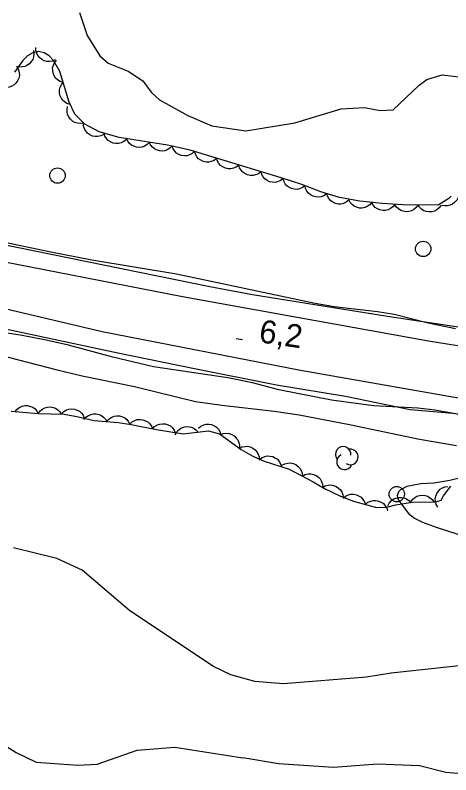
# Model space of a CAD drawing. Extents: x 336540 to 340074, y 5572036 to 5573747.
# Drawn here: x 336923.4 to 336980, y 5572520.4 to 5572619 of the extents above; entities that cross this region are included whole.
import ezdxf

# ---------------------------------------------------------------- set-up
doc = ezdxf.new("R2010")
doc.units = 0
for name, color, linetype in [('Niveau 1', 7, 'Continuous'), ('Niveau 2', 7, 'Continuous'), ('Niveau 21', 7, 'Continuous'), ('Niveau 22', 7, 'Continuous'), ('Niveau 3', 7, 'Continuous'), ('Niveau 36', 7, 'Continuous'), ('Niveau 44', 7, 'Continuous')]:
    doc.layers.add(name, color=color, linetype=linetype)

msp = doc.modelspace()

# ---------------------------------------------------------------- linework, layer by layer
at = {"layer": 'Niveau 1'}
for points in [[(336931.73, 5572619.39), (336932.73, 5572616.38), (336934.39, 5572613.75), (336935.46, 5572612.78), (336938.06, 5572611.74), (336939.97, 5572610.49), (336941.06, 5572609.02), (336942.14, 5572608.04), (336945.79, 5572606.02), (336948.91, 5572604.65), (336953.33, 5572604.03), (336959.72, 5572605.04), (336965.72, 5572606.88), (336968.76, 5572607.04), (336970.8, 5572606.64)], [(336970.8, 5572606.64), (336972.48, 5572606.72), (336975.86, 5572609.93), (336976.85, 5572610.67), (336978.84, 5572611.27), (336982.76, 5572610.81)], [(336981.61, 5572559.04), (336979.84, 5572558.63), (336977.75, 5572558.28), (336976.08, 5572558.18), (336974.23, 5572557.85), (336973.42, 5572557.4), (336973.18, 5572557.17), (336973.01, 5572556.65), (336973.12, 5572556.12), (336974.44, 5572554.35), (336975.25, 5572553.73), (336976.27, 5572553.23), (336978.04, 5572552.57), (336983.66, 5572550.75)], [(336981.45, 5572534.59), (336972.2, 5572533.6), (336969.01, 5572533.11), (336958.23, 5572532.21), (336954.5, 5572532.53), (336951.4, 5572533.39), (336949.15, 5572534.46), (336938.28, 5572541.7), (336932.09, 5572546.97), (336928.79, 5572548.5), (336923.15, 5572549.9)], [(336874.51, 5572538.08), (336878.52, 5572539.31), (336880.05, 5572539.4), (336881.19, 5572539.95), (336882.71, 5572540.03), (336886.84, 5572538.71), (336888.86, 5572538.48), (336893.41, 5572539.05), (336896.45, 5572539.21), (336906.09, 5572536.15), (336907.31, 5572535.37), (336909.87, 5572534.8), (336911.8, 5572533.72), (336913.62, 5572531.27), (336914.36, 5572529.77), (336918.06, 5572526.75), (336923.5, 5572523.3), (336926.1, 5572522.07), (336931.54, 5572521.68), (336934.05, 5572521.82), (336939.22, 5572523.61), (336944.12, 5572524.02), (336952.96, 5572522.62)], [(336982.88, 5572520.42), (336979.29, 5572520.74), (336975.87, 5572521.59), (336970.44, 5572521.81), (336964.71, 5572521.35), (336957.57, 5572521.83), (336952.96, 5572522.62)]]:
    msp.add_lwpolyline(points, dxfattribs=at)
at = {"layer": 'Niveau 2'}
for points in [[(336860.36, 5572601.83), (336879.35, 5572598.2), (336888.35, 5572596.03), (336898.9, 5572593.98), (336904.91, 5572592.45), (336907.38, 5572591.96), (336917.84, 5572590.34), (336921.41, 5572589.69), (336927.81, 5572588.33), (336933.34, 5572587.27), (336944.32, 5572585.43), (336962.33, 5572581.62), (336964.82, 5572581.19), (336970.45, 5572580.58), (336972.58, 5572580.22), (336977.03, 5572579.08), (336980.56, 5572578.37)], [(336981.03, 5572567.18), (336977.9, 5572567.75), (336975.68, 5572568.01), (336969.91, 5572568.32), (336964.45, 5572569.03), (336957.63, 5572570.41), (336954.21, 5572571.29), (336951.01, 5572571.97), (336941.34, 5572573.38), (336936.05, 5572574.63), (336930.31, 5572576.17), (336927.4, 5572576.85), (336924.3, 5572577.44), (336909.1, 5572579.76), (336905.85, 5572580.4), (336893.36, 5572583.16), (336889.93, 5572583.82), (336877.38, 5572586.6), (336870.87, 5572587.91), (336857.82, 5572590.05)]]:
    msp.add_lwpolyline(points, dxfattribs=at)
at = {"layer": 'Niveau 21'}
for points in [[(337100.64, 5572555), (337088.68, 5572555.77), (337076.26, 5572556.91), (337061.77, 5572558.48), (337053.08, 5572559.51), (337036.48, 5572561.54), (337019.9, 5572563.72), (337003.65, 5572566.07), (336997.26, 5572566.87), (336981.42, 5572569.24), (336960.45, 5572572.91), (336934.7, 5572577.9), (336922.06, 5572580.9), (336896.11, 5572586.22), (336883.84, 5572588.4), (336824.78, 5572600.58), (336808.76, 5572603.44), (336772.56, 5572611.03), (336750.71, 5572615.17), (336667.09, 5572632.55), (336658.39, 5572633.88), (336648.84, 5572635.99), (336623.94, 5572640.52), (336607.07, 5572643.16)], [(337095.79, 5572561.86), (337085.79, 5572562.64), (337061.8, 5572564.95), (337045.61, 5572566.7), (337035.77, 5572567.94), (337006.72, 5572571.94), (336977.04, 5572576.7), (336945.1, 5572582.45), (336884.31, 5572594.33), (336807.63, 5572610.39)], [(336854.11, 5572603.04), (336864.11, 5572601.24), (336873.61, 5572598.85), (336882.78, 5572596.77), (336912.98, 5572591.14), (336921.22, 5572589.38), (336948.66, 5572583.79), (336954.19, 5572582.77), (336971.74, 5572579.97), (336983.82, 5572578.15), (337013.25, 5572573.26), (337050.14, 5572568.44), (337060.73, 5572567.18), (337067.1, 5572566.52), (337092.27, 5572564.2)], [(336862, 5572590.65), (336871.76, 5572588.24), (336879.75, 5572586.54), (336884.48, 5572585.66), (336895.01, 5572583.94), (336909.33, 5572581.03), (336936.73, 5572575.18), (336946.66, 5572573.14), (336957.31, 5572571.04), (336966.26, 5572569.58), (336974.67, 5572567.84), (336980.22, 5572567.35), (336984.21, 5572566.84), (336990.44, 5572565.82), (336999.21, 5572564.62), (337006.58, 5572563.3), (337073.99, 5572555.28), (337110.67, 5572552.6)]]:
    msp.add_lwpolyline(points, dxfattribs=at)
at = {"layer": 'Niveau 22'}
msp.add_lwpolyline([(336858.5, 5572587.06), (336869.42, 5572585.02), (336878.23, 5572582.93), (336880.94, 5572582.36), (336884.08, 5572581.82), (336890.68, 5572580.93), (336900.3, 5572578.97), (336912.93, 5572576.76), (336916.31, 5572576.08), (336918.74, 5572575.58), (336928.85, 5572572.98), (336932.08, 5572572.22), (336938.89, 5572570.82), (336946.81, 5572568.87), (336950.22, 5572568.38), (336957.03, 5572567.64), (336960.26, 5572567.15), (336966.82, 5572565.9), (336975.89, 5572564), (336980.68, 5572563.17)], dxfattribs=at)
at = {"layer": 'Niveau 3'}
msp.add_line((336952.1, 5572577.04), (336952.89, 5572576.92), dxfattribs=at)
at = {"layer": 'Niveau 36'}
for centre in [(336928.889, 5572598.201), (336976.369, 5572588.681), (336972.939, 5572556.851)]:
    msp.add_circle(centre, 1, dxfattribs=at)
at = {"layer": 'Niveau 44'}
for points in [[(336928.62, 5572613.23), (336928.24, 5572613.06), (336927.84, 5572613.01), (336927.51, 5572613.01), (336927.17, 5572613.11), (336926.84, 5572613.28), (336926.56, 5572613.53), (336926.33, 5572613.77), (336926.19, 5572614.09), (336926.09, 5572614.45), (336926.08, 5572614.81)], [(336980, 5572595.52), (336979.71, 5572595.23), (336978.33, 5572594.36), (336973.74, 5572594.41), (336971.02, 5572594.58), (336968.13, 5572594.89), (336965.49, 5572595.37), (336963.06, 5572596.11), (336960.6, 5572597.03), (336957.91, 5572597.9), (336946.12, 5572601.48), (336943.18, 5572602.15), (336936.9, 5572603.14), (336934.31, 5572603.86), (336932.44, 5572604.86), (336931.15, 5572606.19), (336930.42, 5572607.72), (336929.18, 5572611.72), (336928.36, 5572613.16), (336927.8, 5572613.74), (336927.14, 5572614.15), (336926.43, 5572614.29), (336925.69, 5572614.12), (336925.01, 5572613.73), (336924.4, 5572613.16), (336923.28, 5572611.63)], [(336925.75, 5572614.42), (336925.82, 5572614.01), (336925.76, 5572613.61), (336925.67, 5572613.29), (336925.48, 5572612.99), (336925.24, 5572612.72), (336924.92, 5572612.5), (336924.63, 5572612.35), (336924.28, 5572612.3), (336923.91, 5572612.29), (336923.56, 5572612.37)], [(336929.63, 5572610.28), (336929.23, 5572610.4), (336928.89, 5572610.63), (336928.64, 5572610.85), (336928.45, 5572611.14), (336928.31, 5572611.49), (336928.26, 5572611.87), (336928.25, 5572612.19), (336928.35, 5572612.53), (336928.51, 5572612.87), (336928.74, 5572613.15)], [(336923.62, 5572612.29), (336923.82, 5572611.92), (336923.9, 5572611.52), (336923.93, 5572611.19), (336923.85, 5572610.85), (336923.71, 5572610.51), (336923.47, 5572610.2), (336923.25, 5572609.97), (336922.94, 5572609.8), (336922.59, 5572609.67), (336922.24, 5572609.63)], [(336930.51, 5572607.42), (336930.11, 5572607.54), (336929.78, 5572607.76), (336929.53, 5572607.98), (336929.34, 5572608.28), (336929.2, 5572608.62), (336929.15, 5572609), (336929.14, 5572609.33), (336929.24, 5572609.67), (336929.4, 5572610), (336929.63, 5572610.28)], [(336932.28, 5572605.02), (336931.87, 5572604.95), (336931.47, 5572605), (336931.15, 5572605.08), (336930.84, 5572605.26), (336930.56, 5572605.51), (336930.35, 5572605.82), (336930.19, 5572606.11), (336930.13, 5572606.46), (336930.12, 5572606.83), (336930.19, 5572607.18)], [(336934.88, 5572603.55), (336934.51, 5572603.36), (336934.11, 5572603.28), (336933.78, 5572603.26), (336933.44, 5572603.34), (336933.1, 5572603.49), (336932.8, 5572603.72), (336932.56, 5572603.95), (336932.4, 5572604.26), (336932.28, 5572604.61), (336932.24, 5572604.97)], [(336937.83, 5572602.88), (336937.51, 5572602.61), (336937.14, 5572602.45), (336936.82, 5572602.36), (336936.47, 5572602.36), (336936.1, 5572602.43), (336935.76, 5572602.59), (336935.48, 5572602.76), (336935.25, 5572603.03), (336935.05, 5572603.34), (336934.94, 5572603.69)], [(336940.81, 5572602.52), (336940.53, 5572602.22), (336940.18, 5572602.01), (336939.87, 5572601.89), (336939.52, 5572601.85), (336939.15, 5572601.88), (336938.79, 5572602), (336938.49, 5572602.14), (336938.23, 5572602.37), (336938, 5572602.66), (336937.85, 5572602.99)], [(336943.78, 5572602.06), (336943.49, 5572601.75), (336943.14, 5572601.55), (336942.83, 5572601.42), (336942.48, 5572601.38), (336942.12, 5572601.41), (336941.75, 5572601.53), (336941.46, 5572601.67), (336941.2, 5572601.91), (336940.97, 5572602.2), (336940.81, 5572602.52)], [(336946.69, 5572601.35), (336946.39, 5572601.06), (336946.02, 5572600.88), (336945.71, 5572600.78), (336945.36, 5572600.77), (336944.99, 5572600.82), (336944.64, 5572600.96), (336944.35, 5572601.12), (336944.11, 5572601.37), (336943.9, 5572601.68), (336943.77, 5572602.02)], [(336949.55, 5572600.44), (336949.23, 5572600.17), (336948.85, 5572600.02), (336948.53, 5572599.94), (336948.18, 5572599.95), (336947.82, 5572600.03), (336947.48, 5572600.2), (336947.2, 5572600.37), (336946.98, 5572600.64), (336946.79, 5572600.97), (336946.68, 5572601.31)], [(336952.42, 5572599.57), (336952.1, 5572599.3), (336951.72, 5572599.15), (336951.4, 5572599.07), (336951.05, 5572599.08), (336950.69, 5572599.16), (336950.35, 5572599.33), (336950.07, 5572599.5), (336949.85, 5572599.77), (336949.66, 5572600.09), (336949.55, 5572600.44)], [(336955.29, 5572598.69), (336954.97, 5572598.43), (336954.59, 5572598.28), (336954.27, 5572598.2), (336953.92, 5572598.21), (336953.56, 5572598.28), (336953.22, 5572598.46), (336952.94, 5572598.63), (336952.72, 5572598.9), (336952.53, 5572599.22), (336952.42, 5572599.57)], [(336958.17, 5572597.82), (336957.84, 5572597.56), (336957.46, 5572597.41), (336957.14, 5572597.32), (336956.79, 5572597.34), (336956.43, 5572597.41), (336956.09, 5572597.58), (336955.81, 5572597.76), (336955.59, 5572598.03), (336955.4, 5572598.35), (336955.29, 5572598.69)], [(336961.02, 5572596.89), (336960.69, 5572596.64), (336960.31, 5572596.49), (336959.99, 5572596.41), (336959.64, 5572596.43), (336959.28, 5572596.52), (336958.94, 5572596.69), (336958.67, 5572596.87), (336958.45, 5572597.15), (336958.26, 5572597.47), (336958.16, 5572597.82)], [(336963.82, 5572595.83), (336963.48, 5572595.58), (336963.1, 5572595.45), (336962.77, 5572595.39), (336962.42, 5572595.43), (336962.07, 5572595.53), (336961.73, 5572595.72), (336961.47, 5572595.91), (336961.26, 5572596.19), (336961.1, 5572596.53), (336961.01, 5572596.88)], [(336980.94, 5572596.46), (336981.02, 5572596.05), (336980.97, 5572595.64), (336980.9, 5572595.32), (336980.72, 5572595.02), (336980.48, 5572594.74), (336980.17, 5572594.51), (336979.89, 5572594.35), (336979.54, 5572594.28), (336979.17, 5572594.27), (336978.82, 5572594.34)], [(336966.71, 5572595), (336966.38, 5572594.74), (336966.01, 5572594.58), (336965.69, 5572594.5), (336965.34, 5572594.51), (336964.97, 5572594.59), (336964.63, 5572594.76), (336964.36, 5572594.94), (336964.13, 5572595.21), (336963.94, 5572595.53), (336963.84, 5572595.87)], [(336969.71, 5572594.72), (336969.44, 5572594.4), (336969.1, 5572594.18), (336968.8, 5572594.04), (336968.45, 5572593.99), (336968.08, 5572593.99), (336967.72, 5572594.1), (336967.41, 5572594.22), (336967.14, 5572594.44), (336966.9, 5572594.72), (336966.73, 5572595.04)], [(336972.7, 5572594.47), (336972.44, 5572594.14), (336972.11, 5572593.91), (336971.82, 5572593.75), (336971.48, 5572593.69), (336971.11, 5572593.68), (336970.73, 5572593.76), (336970.43, 5572593.87), (336970.14, 5572594.08), (336969.89, 5572594.35), (336969.71, 5572594.66)], [(336975.7, 5572594.39), (336975.46, 5572594.05), (336975.14, 5572593.79), (336974.86, 5572593.62), (336974.52, 5572593.54), (336974.15, 5572593.51), (336973.77, 5572593.58), (336973.46, 5572593.67), (336973.17, 5572593.87), (336972.9, 5572594.12), (336972.7, 5572594.42)], [(336978.7, 5572594.36), (336978.46, 5572594.01), (336978.14, 5572593.76), (336977.86, 5572593.59), (336977.52, 5572593.5), (336977.15, 5572593.48), (336976.77, 5572593.54), (336976.46, 5572593.64), (336976.17, 5572593.83), (336975.9, 5572594.09), (336975.7, 5572594.39)], [(336922.88, 5572567.62), (336926.39, 5572567.32), (336929.75, 5572567.22), (336931.38, 5572566.93), (336933.64, 5572566.4), (336936.75, 5572566.13), (336938.47, 5572565.9), (336941.73, 5572565.24), (336945.2, 5572564.67), (336948.49, 5572565.06), (336949.93, 5572564.68), (336952.73, 5572562.65), (336954.26, 5572561.8), (336955.71, 5572561.13), (336958.97, 5572560.11), (336962.07, 5572558.47), (336963.55, 5572557.59), (336965.65, 5572556.59), (336967.33, 5572555.95), (336970.32, 5572555.1), (336971.65, 5572555.17), (336972.83, 5572555.48)], [(336923.4, 5572567.58), (336923.66, 5572567.9), (336924, 5572568.13), (336924.3, 5572568.28), (336924.64, 5572568.34), (336925.01, 5572568.34), (336925.38, 5572568.24), (336925.69, 5572568.13), (336925.97, 5572567.91), (336926.21, 5572567.63), (336926.39, 5572567.32)], [(336926.39, 5572567.32), (336926.63, 5572567.66), (336926.96, 5572567.91), (336927.25, 5572568.07), (336927.59, 5572568.15), (336927.96, 5572568.17), (336928.33, 5572568.09), (336928.64, 5572568), (336928.93, 5572567.79), (336929.2, 5572567.53), (336929.39, 5572567.23)], [(336929.39, 5572567.28), (336929.69, 5572567.58), (336930.04, 5572567.78), (336930.35, 5572567.9), (336930.7, 5572567.93), (336931.07, 5572567.9), (336931.43, 5572567.77), (336931.72, 5572567.62), (336931.98, 5572567.38), (336932.2, 5572567.09), (336932.35, 5572566.76)], [(336932.31, 5572566.52), (336932.57, 5572566.84), (336932.91, 5572567.07), (336933.2, 5572567.21), (336933.55, 5572567.28), (336933.92, 5572567.28), (336934.29, 5572567.18), (336934.6, 5572567.06), (336934.87, 5572566.85), (336935.12, 5572566.57), (336935.3, 5572566.26)], [(336935.3, 5572566.32), (336935.58, 5572566.64), (336935.93, 5572566.85), (336936.23, 5572566.98), (336936.58, 5572567.02), (336936.95, 5572567.01), (336937.31, 5572566.89), (336937.61, 5572566.77), (336937.88, 5572566.53), (336938.12, 5572566.25), (336938.28, 5572565.93)], [(336938.28, 5572565.94), (336938.58, 5572566.23), (336938.94, 5572566.42), (336939.25, 5572566.53), (336939.6, 5572566.55), (336939.97, 5572566.51), (336940.32, 5572566.37), (336940.61, 5572566.22), (336940.86, 5572565.98), (336941.08, 5572565.68), (336941.22, 5572565.34)], [(336941.22, 5572565.32), (336941.5, 5572565.63), (336941.86, 5572565.83), (336942.16, 5572565.95), (336942.51, 5572565.99), (336942.88, 5572565.96), (336943.24, 5572565.83), (336943.54, 5572565.7), (336943.8, 5572565.46), (336944.03, 5572565.16), (336944.18, 5572564.84)], [(336944.17, 5572564.55), (336944.36, 5572564.92), (336944.65, 5572565.21), (336944.91, 5572565.41), (336945.23, 5572565.54), (336945.59, 5572565.62), (336945.98, 5572565.6), (336946.3, 5572565.55), (336946.61, 5572565.39), (336946.91, 5572565.17), (336947.15, 5572564.9)], [(336947.18, 5572565.4), (336947.5, 5572565.68), (336947.87, 5572565.85), (336948.19, 5572565.94), (336948.54, 5572565.94), (336948.9, 5572565.88), (336949.25, 5572565.72), (336949.53, 5572565.55), (336949.77, 5572565.29), (336949.97, 5572564.98), (336950.09, 5572564.64)], [(336950.06, 5572564.59), (336950.45, 5572564.73), (336950.86, 5572564.75), (336951.19, 5572564.72), (336951.52, 5572564.6), (336951.83, 5572564.41), (336952.1, 5572564.13), (336952.3, 5572563.88), (336952.43, 5572563.55), (336952.5, 5572563.18), (336952.49, 5572562.82)], [(336952.47, 5572562.79), (336952.84, 5572562.98), (336953.24, 5572563.05), (336953.57, 5572563.07), (336953.91, 5572562.98), (336954.25, 5572562.83), (336954.55, 5572562.59), (336954.78, 5572562.36), (336954.94, 5572562.05), (336955.06, 5572561.7), (336955.09, 5572561.34)], [(336955.09, 5572561.32), (336955.42, 5572561.58), (336955.8, 5572561.73), (336956.12, 5572561.81), (336956.47, 5572561.8), (336956.83, 5572561.72), (336957.17, 5572561.54), (336957.45, 5572561.37), (336957.67, 5572561.09), (336957.85, 5572560.77), (336957.96, 5572560.43)], [(336958.03, 5572560.61), (336958.4, 5572560.8), (336958.8, 5572560.88), (336959.13, 5572560.9), (336959.47, 5572560.82), (336959.81, 5572560.68), (336960.12, 5572560.44), (336960.35, 5572560.22), (336960.52, 5572559.91), (336960.64, 5572559.56), (336960.68, 5572559.2)], [(336960.68, 5572559.2), (336961.05, 5572559.4), (336961.45, 5572559.48), (336961.78, 5572559.5), (336962.12, 5572559.42), (336962.46, 5572559.28), (336962.77, 5572559.04), (336963, 5572558.82), (336963.17, 5572558.51), (336963.3, 5572558.16), (336963.34, 5572557.8)], [(336963.29, 5572557.71), (336963.65, 5572557.93), (336964.04, 5572558.02), (336964.37, 5572558.06), (336964.72, 5572557.99), (336965.06, 5572557.86), (336965.38, 5572557.64), (336965.62, 5572557.43), (336965.8, 5572557.13), (336965.94, 5572556.78), (336966, 5572556.43)], [(336972.83, 5572555.48), (336974.99, 5572555.8), (336978.03, 5572555.85), (336978.72, 5572556.06), (336979, 5572556.64), (336979.96, 5572557.87)], [(336978.28, 5572555.14), (336978.07, 5572555.5), (336977.97, 5572555.9), (336977.94, 5572556.23), (336978.01, 5572556.57), (336978.14, 5572556.92), (336978.36, 5572557.23), (336978.58, 5572557.48), (336978.88, 5572557.66), (336979.22, 5572557.79), (336979.58, 5572557.84)], [(336965.97, 5572556.34), (336966.29, 5572556.61), (336966.66, 5572556.77), (336966.98, 5572556.85), (336967.33, 5572556.85), (336967.7, 5572556.78), (336968.04, 5572556.61), (336968.32, 5572556.44), (336968.55, 5572556.17), (336968.74, 5572555.86), (336968.86, 5572555.52)], [(336974.73, 5572555.8), (336974.96, 5572556.15), (336975.27, 5572556.41), (336975.55, 5572556.58), (336975.89, 5572556.68), (336976.26, 5572556.72), (336976.64, 5572556.66), (336976.95, 5572556.58), (336977.25, 5572556.39), (336977.52, 5572556.14), (336977.73, 5572555.85)], [(336968.86, 5572555.52), (336969.18, 5572555.79), (336969.55, 5572555.95), (336969.87, 5572556.03), (336970.22, 5572556.03), (336970.58, 5572555.96), (336970.93, 5572555.79), (336971.21, 5572555.62), (336971.44, 5572555.35), (336971.63, 5572555.04), (336971.74, 5572554.7)], [(336971.77, 5572555.32), (336971.95, 5572555.7), (336972.22, 5572556), (336972.48, 5572556.21), (336972.8, 5572556.35), (336973.16, 5572556.43), (336973.54, 5572556.43), (336973.87, 5572556.39), (336974.19, 5572556.24), (336974.49, 5572556.03), (336974.73, 5572555.76)]]:
    msp.add_lwpolyline(points, dxfattribs=at)
for centre, start, end in [((336965.969, 5572562.026), 352.23538, 219.69246), ((336966.916, 5572561.681), 236.90307, 99.58743), ((336966.146, 5572561.039), 114.08157, 339.77016)]:
    msp.add_arc(centre, 1.008, start, end, dxfattribs=at)

# ---------------------------------------------------------------- texts
at = {"layer": 'Niveau 3'}
msp.add_text('6,2    ', height=3, rotation=351.73889, dxfattribs=at).set_placement((336954.94, 5572576.58))

doc.saveas('drawing.dxf')
